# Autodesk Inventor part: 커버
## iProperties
Created: 2012-05
Part Number: 커버
Document SubType Name: 모델링
Designer: SeoGD™
Material: 알루미늄-6061
Mass: 196.659 g
Surface Area: 278.607 cm^2
Volume: 72.5678 cm^3
Density: 2.71 g/cm^3
변환 표준: STEP AP214IS
파일 이름: C:\Users\SeoGD\Desktop\?쒗뿕\而ㅻ쾭-1.stp
전처리기: Build: 253, Release: 2010 SP1 - Date: Wed 07/29/2009
전송 단위: 밀리미터
불확실성: 0.01
Author: SeoGD™
